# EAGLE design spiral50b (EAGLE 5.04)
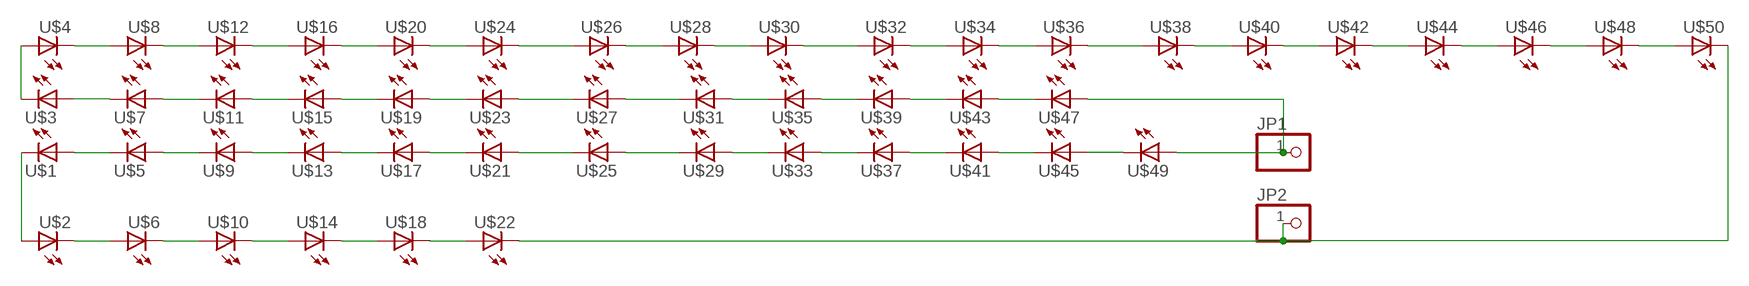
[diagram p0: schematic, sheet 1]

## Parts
JP1  PINHD-1X1  [1X01]
JP2  PINHD-1X1  [1X01]
U$1  LED5MM  [LED5MM]
U$2  LED5MM  [LED5MM]
U$3  LED5MM  [LED5MM]
U$4  LED5MM  [LED5MM]
U$5  LED5MM  [LED5MM]
U$6  LED5MM  [LED5MM]
U$7  LED5MM  [LED5MM]
U$8  LED5MM  [LED5MM]
U$9  LED5MM  [LED5MM]
U$10  LED5MM  [LED5MM]
U$11  LED5MM  [LED5MM]
U$12  LED5MM  [LED5MM]
U$13  LED5MM  [LED5MM]
U$14  LED5MM  [LED5MM]
U$15  LED5MM  [LED5MM]
U$16  LED5MM  [LED5MM]
U$17  LED5MM  [LED5MM]
U$18  LED5MM  [LED5MM]
U$19  LED5MM  [LED5MM]
U$20  LED5MM  [LED5MM]
U$21  LED5MM  [LED5MM]
U$22  LED5MM  [LED5MM]
U$23  LED5MM  [LED5MM]
U$24  LED5MM  [LED5MM]
U$25  LED5MM  [LED5MM]
U$26  LED5MM  [LED5MM]
U$27  LED5MM  [LED5MM]
U$28  LED5MM  [LED5MM]
U$29  LED5MM  [LED5MM]
U$30  LED5MM  [LED5MM]
U$31  LED5MM  [LED5MM]
U$32  LED5MM  [LED5MM]
U$33  LED5MM  [LED5MM]
U$34  LED5MM  [LED5MM]
U$35  LED5MM  [LED5MM]
U$36  LED5MM  [LED5MM]
U$37  LED5MM  [LED5MM]
U$38  LED5MM  [LED5MM]
U$39  LED5MM  [LED5MM]
U$40  LED5MM  [LED5MM]
U$41  LED5MM  [LED5MM]
U$42  LED5MM  [LED5MM]
U$43  LED5MM  [LED5MM]
U$44  LED5MM  [LED5MM]
U$45  LED5MM  [LED5MM]
U$46  LED5MM  [LED5MM]
U$47  LED5MM  [LED5MM]
U$48  LED5MM  [LED5MM]
U$49  LED5MM  [LED5MM]
U$50  LED5MM  [LED5MM]

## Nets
MINUS: JP2.1 U$22.K(C) U$50.K(C)
N$1: U$1.A U$5.K(C)
N$2: U$3.A U$7.K(C)
N$3: U$5.A U$9.K(C)
N$4: U$7.A U$11.K(C)
N$5: U$11.A U$15.K(C)
N$6: U$15.A U$19.K(C)
N$7: U$19.A U$23.K(C)
N$8: U$23.A U$27.K(C)
N$9: U$27.A U$31.K(C)
N$10: U$9.A U$13.K(C)
N$11: U$13.A U$17.K(C)
N$12: U$17.A U$21.K(C)
N$13: U$21.A U$25.K(C)
N$14: U$25.A U$29.K(C)
N$15: U$31.A U$35.K(C)
N$16: U$35.A U$39.K(C)
N$17: U$39.A U$43.K(C)
N$18: U$43.A U$47.K(C)
N$19: U$29.A U$33.K(C)
N$20: U$33.A U$37.K(C)
N$21: U$37.A U$41.K(C)
N$22: U$41.A U$45.K(C)
N$23: U$1.K(C) U$2.A
N$24: U$2.K(C) U$6.A
N$25: U$45.A U$49.K(C)
N$26: U$6.K(C) U$10.A
N$27: U$10.K(C) U$14.A
N$28: U$14.K(C) U$18.A
N$29: U$18.K(C) U$22.A
N$30: U$4.K(C) U$8.A
N$31: U$8.K(C) U$12.A
N$32: U$12.K(C) U$16.A
N$33: U$16.K(C) U$20.A
N$34: U$20.K(C) U$24.A
N$35: U$24.K(C) U$26.A
N$36: U$26.K(C) U$28.A
N$37: U$28.K(C) U$30.A
N$38: U$30.K(C) U$32.A
N$39: U$32.K(C) U$34.A
N$40: U$3.K(C) U$4.A
N$41: U$34.K(C) U$36.A
N$42: U$36.K(C) U$38.A
N$43: U$38.K(C) U$40.A
N$44: U$40.K(C) U$42.A
N$45: U$42.K(C) U$44.A
N$46: U$44.K(C) U$46.A
N$47: U$46.K(C) U$48.A
N$48: U$48.K(C) U$50.A
PLUS: JP1.1 U$47.A U$49.A

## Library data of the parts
JP1 JP2 = pinhead:PINHD-1X1: PIN HEADER
U$1-U$50 = led(2):LED: LED

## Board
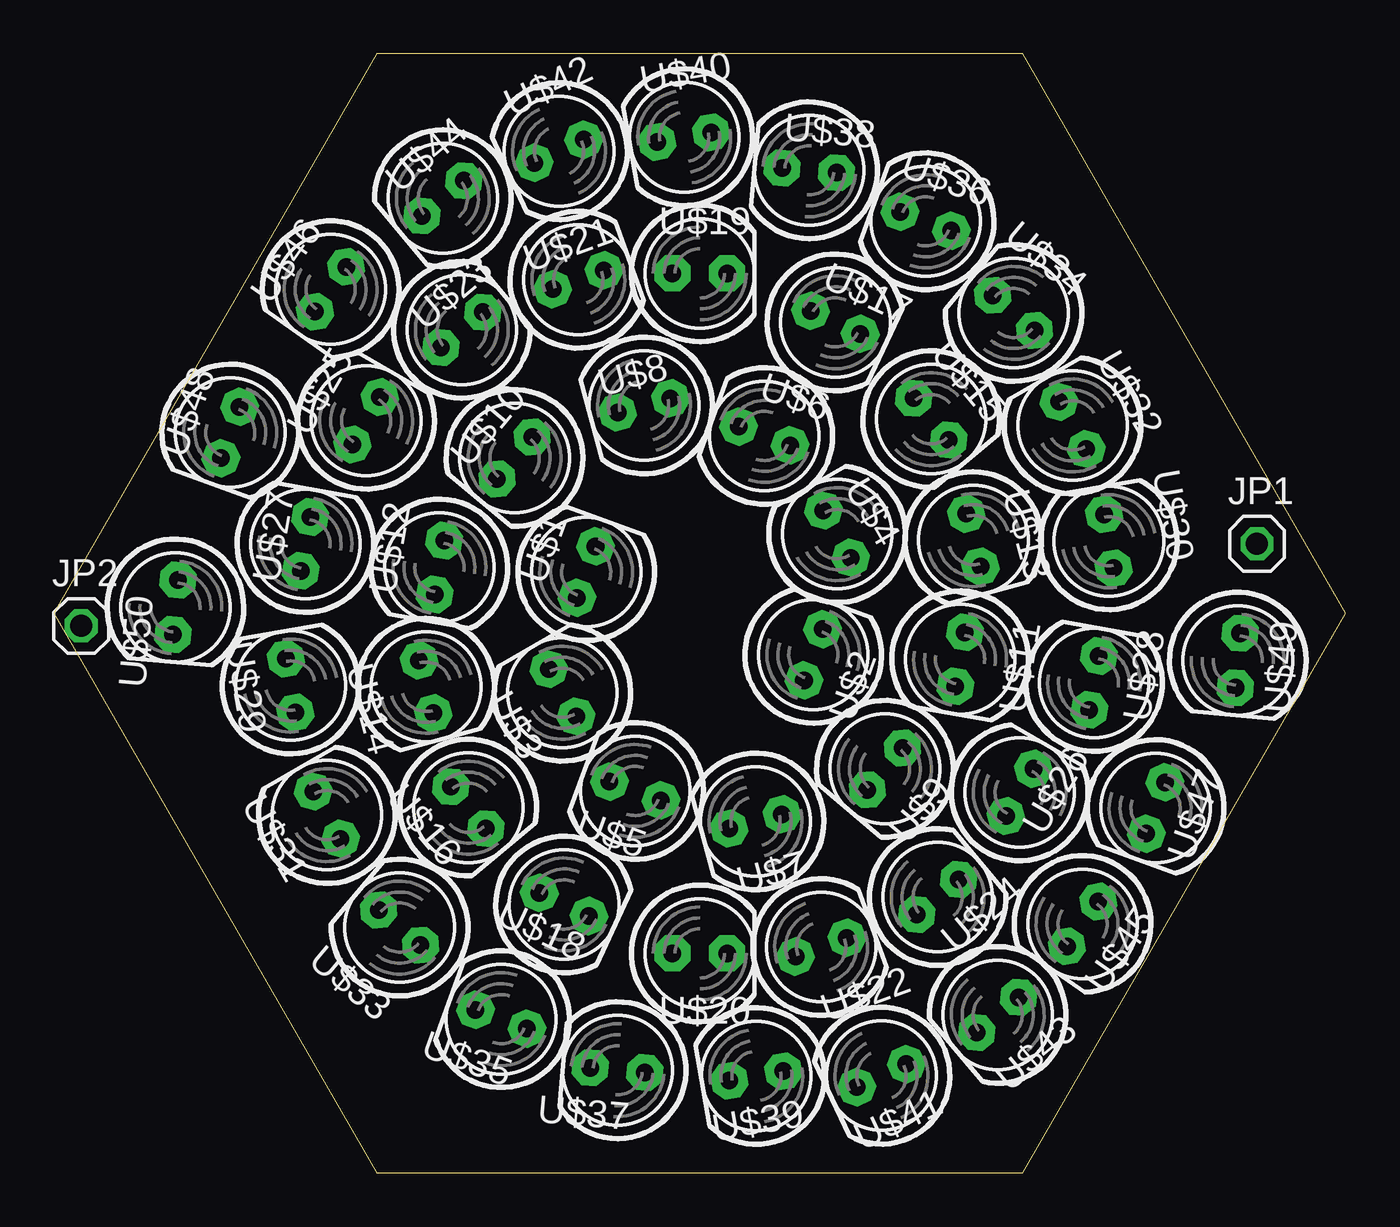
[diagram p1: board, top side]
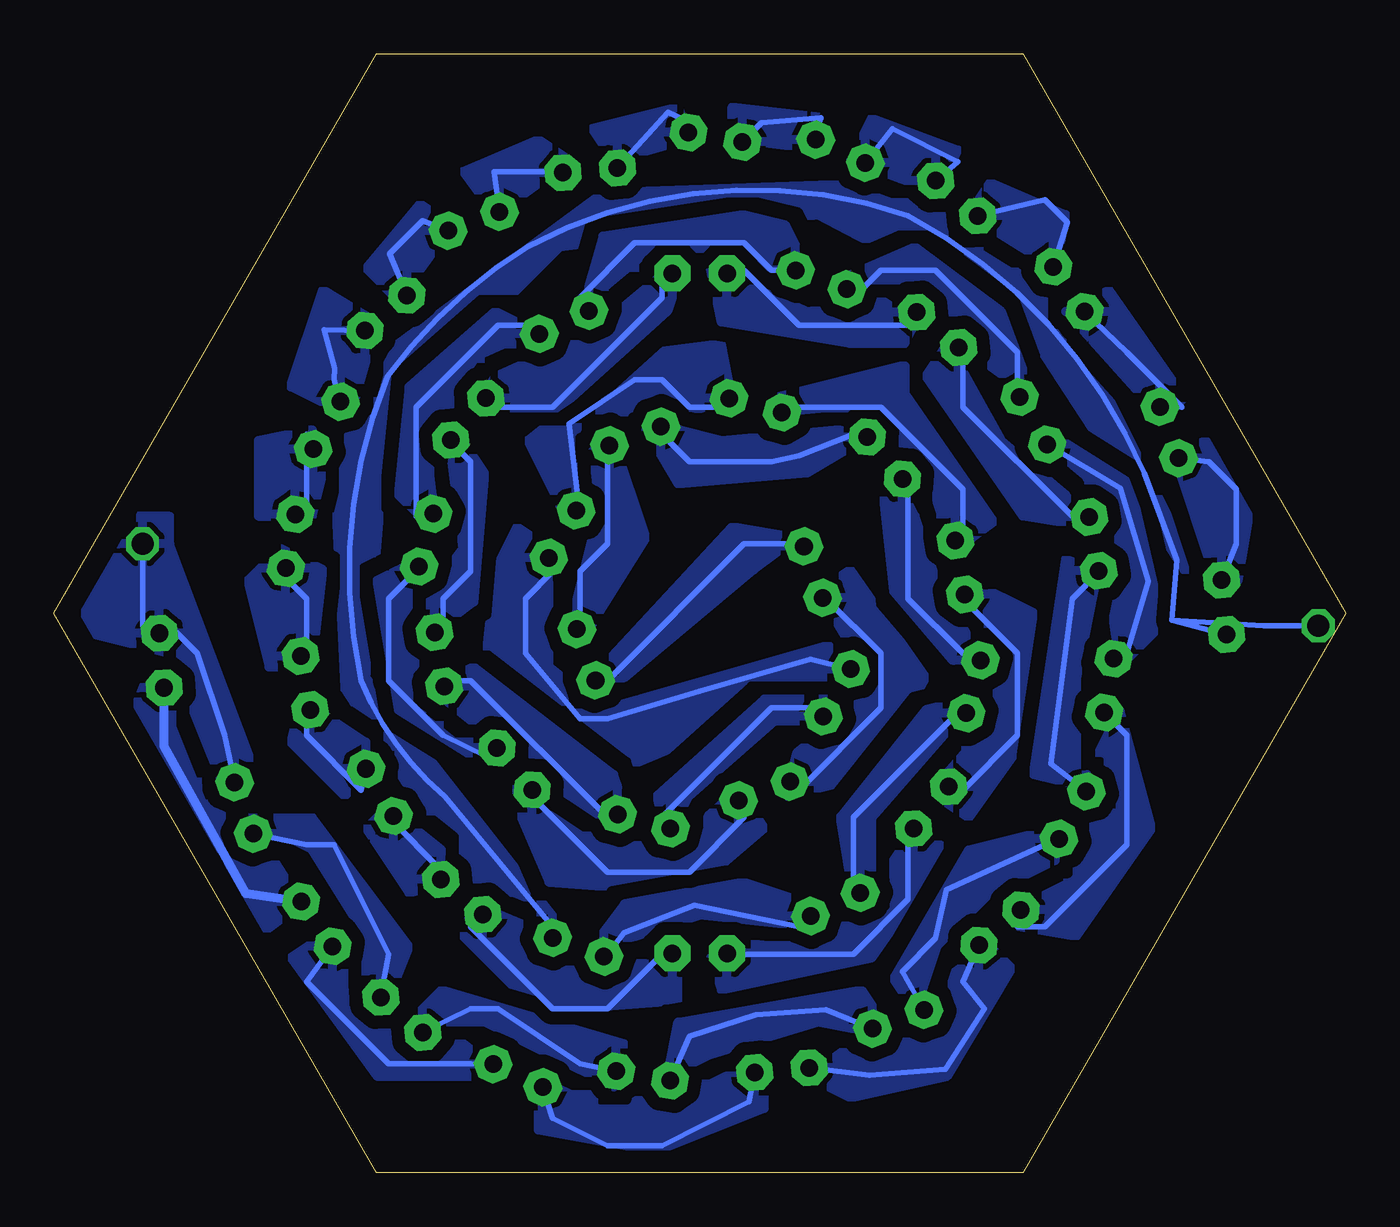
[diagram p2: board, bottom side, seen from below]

Size 60 x 51.96 mm. Coordinates in mm from the lower left corner, seen from the top.
Outline: 15,0 45,0 60,25.98 45,51.96 15,51.96 0,25.98 15,0
Copper layers (1*16): Top 0.035mm / dielectric 1.5mm / Bottom 0.035mm
Design rules "default": minimum track width 10mil, minimum drill 24mil, track to track 8mil, track to pad 8mil, pad to pad 8mil, via to via 8mil, smd to smd 8mil, copper to edge 40mil, drill to drill 8mil, minimum pad ring 10mil, minimum via ring 8mil, stop-mask expansion 4mil, vias tented up to drill 0mil, thermal gap 10mil

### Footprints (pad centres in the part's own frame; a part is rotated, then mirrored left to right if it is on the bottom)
1X01 = drill 1.016 octagon: 1 0,0
LED5MM = drill 0.813 pad 1.676 octagon: A -1.27,0; K 1.27,0

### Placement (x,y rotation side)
JP1  55.88,29.21 0 top
JP2  1.27,25.4 0 top
U$1  24.73,27.9 70 top
U$2  35.27,24.06 70 top
U$3  23.62,22.3 120 top
U$4  36.38,29.66 120 top
U$5  27,17.74 160 top
U$6  33,34.22 160 top
U$7  32.59,16.32 195 top
U$8  27.41,35.64 195 top
U$9  38.6,18.76 230 top
U$10  21.4,33.2 230 top
U$11  42.09,23.85 260 top
U$12  17.91,28.11 260 top
U$13  42.71,29.38 285 top
U$14  17.29,22.58 285 top
U$15  40.75,35 310 top
U$16  19.25,16.96 310 top
U$17  36.3,39.49 335 top
U$18  23.7,12.47 335 top
U$19  30,41.77 0 top
U$20  30,10.19 0 top
U$21  24.36,41.47 20 top
U$22  35.64,10.49 20 top
U$23  18.95,39.15 40 top
U$24  41.05,12.81 40 top
U$25  14.51,34.93 59.9 top
U$26  44.86,17.67 59.9 top
U$27  11.69,29.21 80 top
U$28  48.31,22.75 80 top
U$29  11,22.63 100 top
U$30  49,29.33 100 top
U$31  12.68,16.62 120 top
U$32  47.32,34.71 120 top
U$33  16.06,11.39 140 top
U$34  44.57,39.93 140 top
U$35  20.78,7.14 160 top
U$36  40.49,44.18 160 top
U$37  26.18,4.77 175 top
U$38  35.09,46.55 175 top
U$39  32.63,4.5 190 top
U$40  29.28,48.09 190 top
U$41  38.44,4.52 205 top
U$42  23.46,47.44 205 top
U$43  43.84,7.34 220 top
U$44  18.07,45.26 220 top
U$45  47.78,11.56 235 top
U$46  12.86,41.03 235 top
U$47  51.17,16.95 250 top
U$48  8.19,34.38 250 top
U$49  54.99,23.79 265 top
U$50  5.65,26.26 265 top

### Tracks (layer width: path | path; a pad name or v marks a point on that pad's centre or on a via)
MINUS
  Bottom 0.254: JP2.1 3.81,25.4 8.08,25.67 | 8.08,25.67 7.85,28.44 9.35,32.48 arc-39 20.32,44.45 arc-47 38,43 arc-22 44.5,37 arc-35 45.72,22.86 arc-28 41.83,17.47 36.83,11.43 U$22.K | 8.08,25.67 U$50.K
  pour Bottom (isolate 0.61, rank 3): 36.5,11.5 45.5,23 44.5,35 36.5,43 24.5,44.5 15,39.5 7.5,28 7,28 13,40 20.5,46 34.5,45.5 44,38.5 47,33 46.5,22.5 41,14 39,12.5
N$1
  Bottom 0.254: U$5.K 25.4,17.78 21.59,21.59 21.59,24.13 24.13,26.67 U$1.A
  pour Bottom (isolate 0.61, rank 2): 26,17.5 22,18.5 19.5,23 23,28 24.5,27 23,24.5 23,21.5 25.5,19.5
N$2
  Bottom 0.254: U$3.A 24.13,21.59 26.67,21.59 31.75,16.51 U$7.K
  pour Bottom (isolate 0.61): 24,22 27,22 32,17.5 31.5,15.5 30.5,17.5 26.5,21 24.5,21
N$3
  Bottom 0.254: U$5.A 27.94,16.51 30.48,13.97 34.29,13.97 38.1,17.78 U$9.K
  pour Bottom (isolate 0.61, rank 2): 38.5,18 38.5,17 37,13.5 30.5,13 27,16 28,17.5
N$4
  Bottom 0.254: U$7.A 34.29,16.51 40.64,22.86 41.91,22.86 U$11.K
  pour Bottom (isolate 0.61): 33.5,17 34,18.5 40.5,23.5 42.5,22.5 37.5,18.5 34.5,16.5
N$5
  Bottom 0.254: U$11.A 41.91,25.4 41.91,26.67 40.64,27.94 40.64,33.02 41.91,34.29 U$15.K
  pour Bottom (isolate 0.61): 41,34 40,32.5 40.5,26.5 42.5,25 42.5,27 41,29 41.5,33
N$6
  Bottom 0.254: U$19.K 31.75,41.91 31.75,40.64 36.83,35.56 39.37,35.56 U$15.A
  pour Bottom (isolate 0.61): 31,41.5 31.5,40 36.5,35.5 40.5,35.5 39.5,37 35,39 32,41.5
N$7
  Bottom 0.254: U$23.K 20.32,39.37 25.4,39.37 27.94,41.91 U$19.A
  pour Bottom (isolate 0.61): 20,39.5 20.5,38.5 23,38.5 29,39.5 29.5,42 25,40 21.5,40.5
N$8
  Bottom 0.254: U$27.K 12.7,30.48 17.78,35.56 17.78,38.1 U$23.A
  pour Bottom (isolate 0.61): 12,30 15,30.5 19.5,37 18.5,38.5 16,34 13,31.5
N$9
  Bottom 0.254: U$31.K 13.7,19.01 12.7,26.67 11.43,27.94 U$27.A
  pour Bottom (isolate 0.61): 12.5,18 14.5,18.5 13,28.5 11.5,28 12.5,23 12.5,18.5 12,18.5 11.5,17.5
N$10
  Bottom 0.254: U$9.A 39.87,19.32 41.91,20.32 44.45,22.86 44.45,26.67 43.18,27.94 U$13.K
  pour Bottom (isolate 0.61, rank 2): 43,28.5 45,27.5 44,21.5 40,19 39.5,20
N$11
  Bottom 0.254: U$13.A 43.18,30.48 43.18,35.56 39.37,39.37 38.1,39.37 U$17.K
  pour Bottom (isolate 0.61, rank 2): 37.5,39 39.5,40 43.5,36.5 44,31.5 43,30.5
N$12
  Bottom 0.254: U$21.K 25.4,41.91 26.67,41.91 27.94,43.18 33.02,43.18 35.56,40.64 U$17.A
  pour Bottom (isolate 0.61, rank 2): 25,42 26,44 28,44.5 34.5,43.5 35.5,40 32.5,42
N$13
  Bottom 0.254: U$25.K 15.24,36.83 15.24,38.1 19.05,41.91 21.59,41.91 22.86,40.64 U$21.A
  pour Bottom (isolate 0.61, rank 2): 14.5,36 16,40 20,43 23.5,41.5 20,40
N$14
  Bottom 0.254: U$29.K 10.16,24.13 9.16,27.48 10.47,31.79 U$25.A
  pour Bottom (isolate 0.61, rank 2): 10.5,23.5 8.5,25.5 10,32 14,34.5 11.5,30.5
N$15
  Bottom 0.254: U$35.K 20.59,9.35 19.05,10.89 18.55,13.16 13.97,15.24 U$31.A
  pour Bottom (isolate 0.61): 20,7.5 21,9 17.5,15 13.5,16 13.5,14.5 16.5,13 19,10.5
N$16
  Bottom 0.254: U$39.K 30.48,6.35 27.4,7.35 24.13,7.58 U$35.A
  pour Bottom (isolate 0.61): 31.5,4.5 31,7 22.5,8.5 21.5,7 22,6.5 24.5,7 29.5,5.5
N$17
  Bottom 0.254: U$39.A 35.56,5.08 39.37,7.62 40.64,7.62 U$43.K
  pour Bottom (isolate 0.61): 43.5,7 42,8.5 33.5,6 34,4 37,5.5 40,7
N$18
  Bottom 0.254: U$43.A 44.45,10.16 46.99,15.24 48.26,15.24 U$47.K
  pour Bottom (isolate 0.61): 51,16.5 48,16.5 43.5,10.5 44.5,8 45.5,8.5 45.5,11 48,15
N$19
  Bottom 0.254: U$33.K 15.24,11.43 13.97,11.43 10.16,15.24 10.16,20.32 11.43,21.59 U$29.A
  pour Bottom (isolate 0.61, rank 2): 15.5,11.5 12.5,11 9,16 10.5,21.5
N$20
  Bottom 0.254: U$37.K 22.13,4.54 18.59,4.81 16.78,7.62 17.78,8.89 U$33.A
  pour Bottom (isolate 0.61, rank 2): 25,4.5 23,3.5 18.5,4.5 15.5,9.5 16.5,10.5
N$21
  Bottom 0.254: U$37.A 27.71,3.31 31.75,1.27 34.29,1.27 36.83,2.54 U$41.K
  pour Bottom (isolate 0.61, rank 2): 37.5,4.5 37.5,2 32,1 27,3 27,4.5
N$22
  Bottom 0.254: U$41.A 40.64,5.08 44.45,5.08 48.26,8.89 U$45.K
  pour Bottom (isolate 0.61, rank 2): 47.5,11 49,10 45,4.5 39,4.5
N$23
  Bottom 0.254: U$1.K 25.4,29.21 27.94,29.21 34.29,22.86 U$2.A
  pour Bottom (isolate 0.61): 25.5,29.5 28.5,30 35,23 33.5,23 27.5,28
N$24
  Bottom 0.254: U$2.K 35.56,25.4 35.56,27.94 34.29,29.21 34.29,33.02 U$6.A
  pour Bottom (isolate 0.61): 35,25.5 32.5,29.5 34,34 35,33.5 35,29.5 36,25.5
N$25
  Bottom 0.406: U$45.A 51.07,12.97 54.88,19.82 U$49.K
  pour Bottom (isolate 0.61, rank 2): 55.5,23.5 56.5,21 50.5,11 48.5,12.5
N$26
  Bottom 0.254: U$10.A 22.86,34.29 25.4,33.29 26.67,33.02 30.48,33.02 31.75,34.29 U$6.K
  pour Bottom (isolate 0.61): 32.5,34.5 31,32 25,32.5 22.5,34 23.5,34.5 29,34 31,34.5
N$27
  Bottom 0.254: U$14.A 16.51,24.13 17.78,24.13 20.32,26.67 20.32,31.75 U$10.K
  pour Bottom (isolate 0.61): 21,32.5 21.5,31.5 21,27 18,23.5 17,24 19,27.5 20,30.5
N$28
  Bottom 0.254: U$14.K 17.78,21.59 22.86,16.51 22.86,12.7 U$18.A
  pour Bottom (isolate 0.61): 17.5,22 19.5,21.5 23.5,16.5 23,13.5 22,13 22,16.5 18.5,20.5
N$29
  Bottom 0.254: U$22.A 34.29,10.16 33.52,11.16 30.25,12.43 25.4,11.43 U$18.K
  pour Bottom (isolate 0.61): 25,12.5 28,13.5 33.5,12.5 35,10.5 33,11 30,12 25.5,11.5
N$30
  Bottom 0.254: U$8.A 29.21,35.56 30.48,35.56 31.75,36.83 33.02,36.83 36.06,34.79 35.56,30.48 U$4.K
  pour Bottom (isolate 0.61, rank 2): 28.5,36 29,38.5 33,38 38,34 36.5,31 34.5,34
N$31
  Bottom 0.254: U$12.A 17.78,29.21 17.78,31.75 21.59,35.56 25.4,35.56 U$8.K
  pour Bottom (isolate 0.61, rank 2): 18,29 16,30.5 20.5,37.5 26.5,36 24.5,35
N$32
  Bottom 0.254: U$12.K 17.78,26.67 15.24,24.13 15.24,20.32 17.78,17.78 U$16.A
  pour Bottom (isolate 0.61, rank 2): 19,17.5 17.5,16.5 15,20 14.5,26 17.5,27.5 16.5,24
N$33
  Bottom 0.254: U$20.A 27.94,10.16 22.86,10.16 20.32,12.7 20.32,15.24 U$16.K
  pour Bottom (isolate 0.61, rank 2): 29.5,10 29,8.5 22,10 18.5,15 20,16 22,13
N$34
  Bottom 0.254: U$20.K 31.75,10.16 34.29,7.62 36.83,7.62 40.64,11.43 U$24.A
  pour Bottom (isolate 0.61, rank 2): 40.5,12.5 41,11 37.5,7.5 31,8 31,9.5 34.5,10
N$35
  Bottom 0.254: U$24.K 41.91,13.97 44.45,16.51 U$26.A
  pour Bottom (isolate 0.61, rank 2): 44.5,17 45.5,16 43.5,13 41.5,13.5 42,15
N$36
  Bottom 0.254: U$26.K 45.72,17.78 48.26,20.32 48.26,21.59 U$28.A
  pour Bottom (isolate 0.61, rank 2): 48.5,22 49,20 46.5,17.5 45,19 45.5,20
N$37
  Bottom 0.254: U$28.K 48.26,24.13 48.26,26.67 49.53,27.94 U$30.A
  pour Bottom (isolate 0.61, rank 2): 49.5,29 51,27.5 50,23.5 48,23.5 47.5,28
N$38
  Bottom 0.254: U$32.A 48.26,34.29 48.26,30.48 U$30.K
  pour Bottom (isolate 0.61): 48,34.5 50.5,34 50.5,30.5 48,30.5 47.5,32.5
N$39
  Bottom 0.254: U$32.K 46.99,36.83 46.95,37.37 47.45,39.14 U$34.A
  pour Bottom (isolate 0.61): 47,35.5 49,36.5 47.5,41 45,39.5 46,36
N$40
  Bottom 0.254: U$3.K 24.86,23.86 30.02,22.36 34.29,21.09 35.56,21.09 38.1,24.13 38.1,26.67 36.83,27.94 U$4.A
  pour Bottom (isolate 0.61, rank 2): 37,29 38.5,30 39.5,28 40,23.5 33,19 23.5,23 24,24.5 34.5,21.5 37,23.5
N$41
  Bottom 0.254: U$36.A 42.87,44.22 44.41,42.68 U$34.K
  pour Bottom (isolate 0.61): 44,40.5 45.5,42 43,45 41.5,44
N$42
  Bottom 0.254: U$38.A 37.02,46.49 39.56,46.49 U$36.K
  pour Bottom (isolate 0.61): 39.5,44.5 41,46.5 37.5,48 36,47
N$43
  Bottom 0.254: U$40.A 30.44,48.76 31.48,49.26 U$38.K
  pour Bottom (isolate 0.61): 34,47 35,48.5 31,49.5 30.5,48
N$44
  Bottom 0.254: U$42.A 24.59,48.49 24.36,48.99 27.13,48.76 U$40.K
  pour Bottom (isolate 0.61): 28.5,48 28.5,49.5 24,49 24.5,47.5
N$45
  Bottom 0.254: U$44.A 18.01,46.95 21.05,48.49 U$42.K
  pour Bottom (isolate 0.61): 23,47 22,49 18,47.5 19,45.5
N$46
  Bottom 0.254: U$46.A 12.93,44.14 13.97,45.18 U$44.K
  pour Bottom (isolate 0.61): 17.5,44.5 16.5,46 13,44.5 13.5,42
N$47
  Bottom 0.254: U$48.A 7.62,35.56 10.16,38.1 U$46.K
  pour Bottom (isolate 0.61): 13,40 11,41 7.5,36 8.5,35
N$48
  Bottom 0.254: U$50.A 5.08,29.21 5.08,31.75 6.35,33.02 U$48.K
  pour Bottom (isolate 0.61): 8,33.5 6.5,34 4.5,30.5 5,27.5 6,27.5
PLUS
  Bottom 0.254: JP1.1 55.88,25.4 U$49.A 54.61,25.4 53.34,24.13 52.07,20.32 U$47.A
  pour Bottom (isolate 0.61): 54.61,30.48 57.15,30.48 59.69,25.4 54.61,24.13 52.07,17.78 50.8,19.05 54.61,29.21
